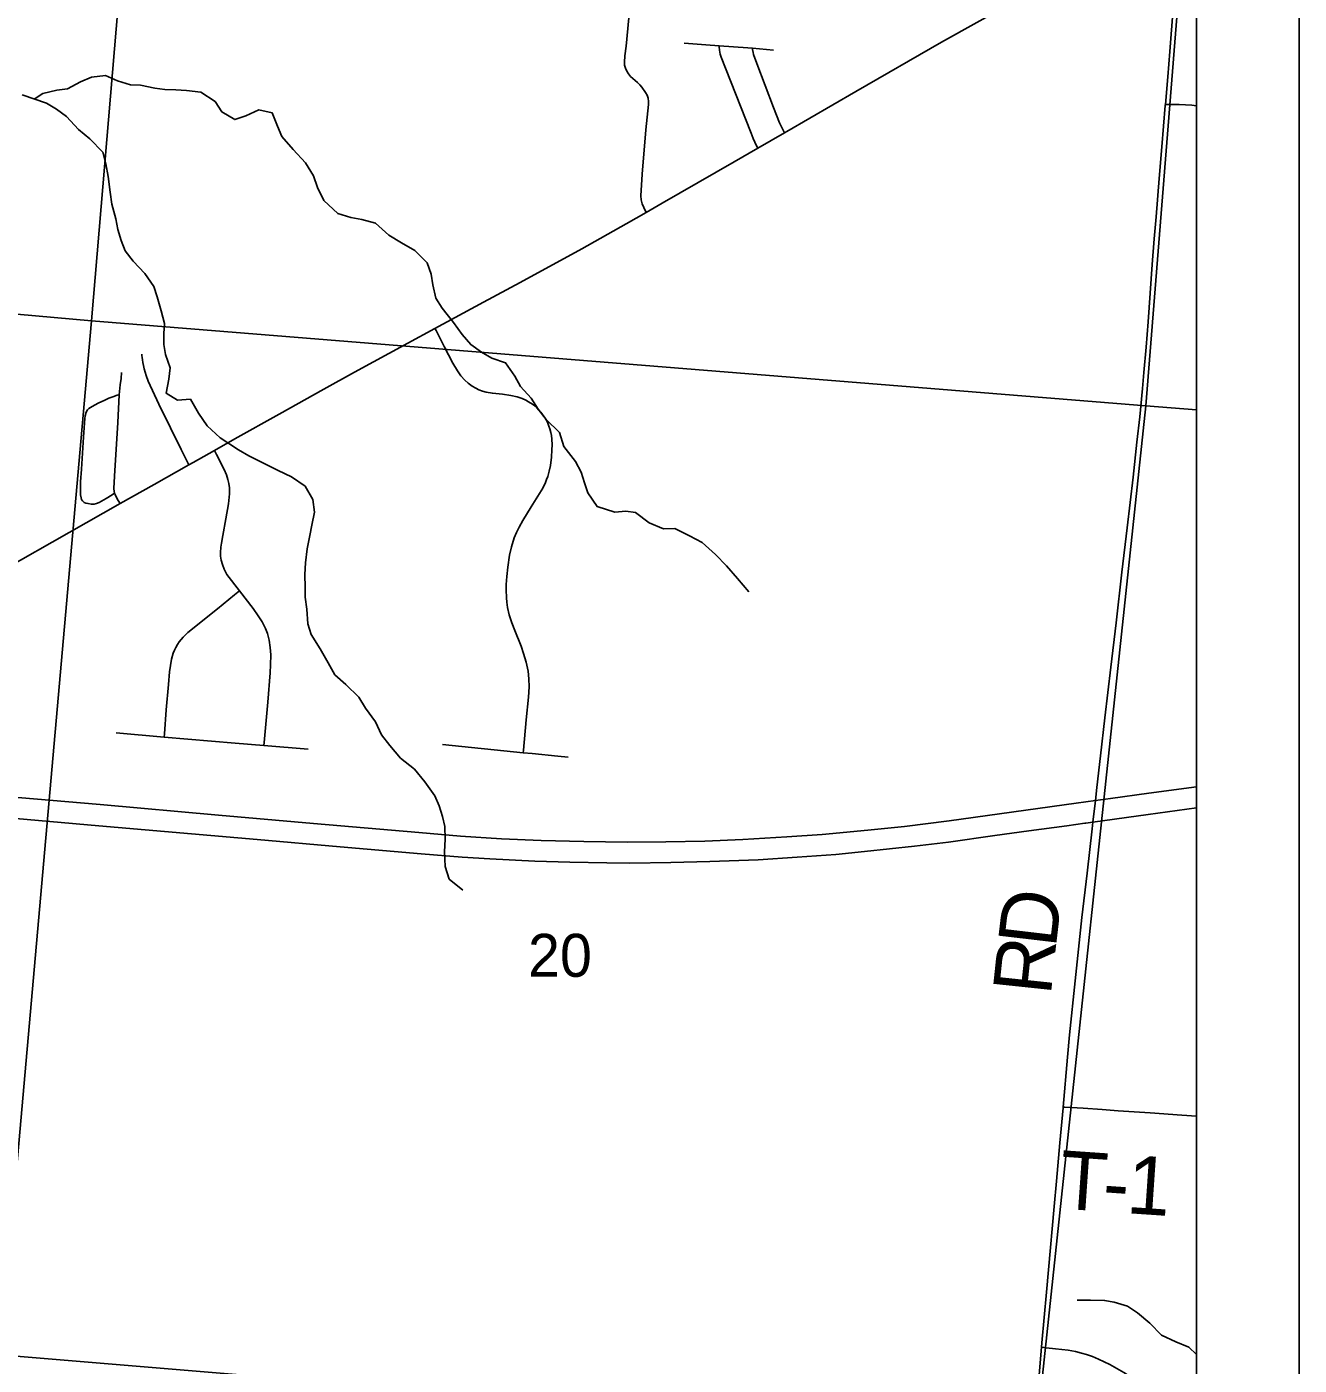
# Model space of a CAD drawing. Extents: x 831 to 1552, y 430 to 870.
# Drawn here: x 1363.98 to 1388.77, y 678.59 to 704.66 of the extents above; entities that cross this region are included whole.
import ezdxf

# ---------------------------------------------------------------- set-up
doc = ezdxf.new("R2010")
doc.units = 0
for name, color, linetype in [('GM_X_Corporation', 7, 'Continuous'), ('GM_X_County_Road', 7, 'Continuous'), ('GM_X_Interstate_Route', 7, 'Continuous'), ('GM_X_Minor_River', 7, 'Continuous'), ('GM_X_Section_Text', 7, 'Continuous'), ('GM_X_Township_Road', 7, 'Continuous'), ('GM_X_Township_Road_Text', 7, 'Continuous'), ('SH_Data', 7, 'Continuous')]:
    doc.layers.add(name, color=color, linetype=linetype)

msp = doc.modelspace()

# ---------------------------------------------------------------- linework, layer by layer
at = {"layer": 'GM_X_Corporation'}
msp.add_lwpolyline([(1386.766, 650.938), (1386.766, 724.317)], dxfattribs=at)
for points in [[(1347.89, 720.702), (1366.951, 719.126), (1365.244, 698.931), (1346.049, 700.645)], [(1386.766, 709.654), (1386.766, 717.659), (1366.951, 719.126), (1365.244, 698.931), (1385.781, 697.271)], [(1386.766, 697.192), (1386.766, 709.654), (1385.781, 697.271)], [(1346.049, 700.645), (1365.244, 698.931), (1363.462, 678.79), (1343.776, 680.603)], [(1365.244, 698.931), (1385.781, 697.271), (1383.627, 677.106), (1363.462, 678.79)], [(1386.766, 676.871), (1386.766, 697.192), (1385.781, 697.271), (1383.627, 677.106)], [(1363.462, 678.79), (1383.627, 677.106), (1381.941, 657.229), (1361.881, 658.872), (1361.646, 658.883)]]:
    msp.add_lwpolyline(points, close=True, dxfattribs=at)
at = {"layer": 'GM_X_County_Road'}
msp.add_line((1378.22, 702.291), (1378.739, 702.59), dxfattribs=at)
for points in [[(1378.739, 702.59), (1378.784, 702.616), (1380.13, 703.393), (1381.801, 704.353), (1383.804, 705.482), (1386.134, 706.793), (1386.444, 706.965)], [(1376.048, 701.038), (1376.362, 701.217), (1377.761, 702.026), (1378.22, 702.291)], [(1371.933, 698.782), (1372.882, 699.293), (1373.593, 699.676), (1374.793, 700.331), (1375.66, 700.818), (1376.048, 701.038)], [(1367.64, 696.404), (1368.035, 696.627), (1368.903, 697.113), (1369.77, 697.599), (1370.368, 697.93), (1371.405, 698.496), (1371.933, 698.782)], [(1367.14, 696.123), (1367.223, 696.169), (1367.64, 696.404)], [(1365.804, 695.368), (1366.465, 695.742), (1367.14, 696.123)], [(1358.462, 691.217), (1359.016, 691.539), (1360.01, 692.09), (1360.667, 692.459), (1361.512, 692.939), (1362.529, 693.516), (1365.804, 695.368)]]:
    msp.add_lwpolyline(points, dxfattribs=at)
at = {"layer": 'GM_X_Interstate_Route'}
msp.add_line((1384.592, 689.142), (1384.612, 689.145), dxfattribs=at)
for points in [[(1384.797, 689.584), (1385.092, 689.624), (1385.839, 689.728), (1386.766, 689.853)], [(1363.508, 689.669), (1365.413, 689.506), (1367.717, 689.301), (1369.57, 689.137), (1371.617, 688.96), (1372.43, 688.894), (1373.229, 688.842), (1374.004, 688.807), (1374.832, 688.786), (1375.68, 688.776), (1376.43, 688.779), (1377.188, 688.797), (1377.932, 688.828), (1378.787, 688.877), (1379.475, 688.925), (1380.365, 689.009), (1381.077, 689.082), (1381.95, 689.193), (1384.421, 689.534), (1384.797, 689.584)], [(1363.249, 689.278), (1365.391, 689.094), (1368.473, 688.825), (1370.087, 688.685), (1371.664, 688.549), (1372.465, 688.485), (1373.001, 688.449), (1373.878, 688.405), (1374.559, 688.385), (1375.283, 688.373), (1375.732, 688.365), (1376.525, 688.377), (1377.285, 688.397), (1378.23, 688.433), (1378.991, 688.481), (1379.743, 688.537), (1380.3, 688.593), (1381.273, 688.697), (1381.933, 688.777), (1382.838, 688.901), (1383.503, 688.993), (1384.243, 689.094), (1384.592, 689.142)], [(1384.612, 689.145), (1384.747, 689.164), (1385.821, 689.314), (1386.766, 689.443)]]:
    msp.add_lwpolyline(points, dxfattribs=at)
at = {"layer": 'GM_X_Minor_River'}
for points in [[(1364.131, 703.248), (1364.296, 703.357), (1364.57, 703.422), (1364.776, 703.45), (1365.028, 703.583), (1365.242, 703.672), (1365.516, 703.707), (1365.75, 703.605), (1366.007, 703.526), (1366.197, 703.516), (1366.478, 703.46), (1366.675, 703.435), (1366.887, 703.425), (1367.092, 703.415), (1367.373, 703.381), (1367.652, 703.203), (1367.786, 702.997), (1368.035, 702.849), (1368.249, 702.923), (1368.501, 703.041), (1368.766, 702.977), (1368.869, 702.718), (1368.95, 702.52), (1369.175, 702.267), (1369.415, 702.006), (1369.571, 701.753), (1369.644, 701.524), (1369.77, 701.272), (1370.041, 701.019), (1370.298, 700.94), (1370.51, 700.899), (1370.775, 700.828), (1371.038, 700.597), (1371.28, 700.45), (1371.544, 700.295), (1371.784, 700.057), (1371.857, 699.836), (1371.893, 699.63), (1371.95, 699.371), (1372.077, 699.172), (1372.294, 698.896), (1372.466, 698.659), (1372.63, 698.467), (1372.841, 698.321), (1373.045, 698.204), (1373.31, 698.11), (1373.489, 697.85), (1373.6, 697.651), (1373.81, 697.421), (1373.944, 697.207), (1374.101, 697.007), (1374.357, 696.754), (1374.444, 696.479), (1374.669, 696.188), (1374.78, 695.982), (1374.846, 695.776), (1374.912, 695.578), (1375.091, 695.31), (1375.439, 695.2), (1375.652, 695.22), (1375.842, 695.195), (1376.105, 694.994), (1376.385, 694.877), (1376.605, 694.882), (1376.892, 694.742), (1377.141, 694.61), (1377.397, 694.379), (1377.614, 694.157), (1377.824, 693.911), (1378.048, 693.65)], [(1363.893, 703.331), (1364.37, 703.166), (1364.566, 703.05), (1364.761, 702.911), (1364.994, 702.657), (1365.212, 702.472), (1365.467, 702.211), (1365.525, 701.983), (1365.567, 701.739), (1365.609, 701.435), (1365.644, 701.199), (1365.717, 700.917), (1365.76, 700.704), (1365.826, 700.491), (1365.899, 700.293), (1366.056, 700.093), (1366.281, 699.848), (1366.46, 699.595), (1366.526, 699.397), (1366.599, 699.123), (1366.664, 698.879), (1366.654, 698.682), (1366.652, 698.469), (1366.687, 698.271), (1366.775, 698.012), (1366.75, 697.792), (1366.701, 697.519), (1366.919, 697.38), (1367.17, 697.4), (1367.326, 697.132), (1367.498, 696.88), (1367.754, 696.649), (1368.108, 696.417), (1368.311, 696.301), (1368.598, 696.153), (1368.878, 696.013), (1369.142, 695.889), (1369.406, 695.711), (1369.554, 695.451), (1369.589, 695.2), (1369.533, 694.95), (1369.5, 694.745), (1369.444, 694.488), (1369.41, 694.215), (1369.4, 693.987), (1369.404, 693.737), (1369.409, 693.547), (1369.437, 693.311), (1369.456, 693.03), (1369.522, 692.816), (1369.701, 692.541), (1369.857, 692.266), (1369.983, 692.036), (1370.201, 691.844), (1370.449, 691.598), (1370.583, 691.384), (1370.777, 691.116), (1370.896, 690.864), (1371.053, 690.657), (1371.262, 690.412), (1371.533, 690.196), (1371.735, 689.951), (1371.93, 689.675), (1372.018, 689.484), (1372.084, 689.271), (1372.127, 689.08), (1372.132, 688.83), (1372.121, 688.587), (1372.133, 688.298), (1372.213, 688.054), (1372.477, 687.839)], [(1386.766, 678.795), (1386.619, 678.941), (1386.362, 679.042), (1386.083, 679.175), (1385.857, 679.405), (1385.617, 679.605), (1385.421, 679.737), (1385.164, 679.816), (1384.974, 679.848), (1384.701, 679.851), (1384.442, 679.854)]]:
    msp.add_lwpolyline(points, dxfattribs=at)
at = {"layer": 'GM_X_Township_Road'}
for p, q in [((1378.117, 704.237), (1378.527, 704.201)), ((1365.726, 690.903), (1366.662, 690.822)), ((1368.604, 690.654), (1369.467, 690.584)), ((1372.083, 690.676), (1373.653, 690.517))]:
    msp.add_line(p, q, dxfattribs=at)
for points in [[(1386.16, 703.143), (1386.205, 703.68), (1386.246, 704.176), (1386.309, 705.011)], [(1376.048, 701.038), (1376.041, 701.053), (1376.002, 701.135), (1375.971, 701.207), (1375.951, 701.282), (1375.943, 701.36), (1375.972, 701.785), (1376.042, 702.648), (1376.095, 703.141), (1376.096, 703.202), (1376.088, 703.264), (1376.067, 703.322), (1376.036, 703.375), (1375.966, 703.477), (1375.926, 703.525), (1375.881, 703.568), (1375.786, 703.647), (1375.742, 703.69), (1375.704, 703.738), (1375.671, 703.791), (1375.645, 703.847), (1375.628, 703.907), (1375.623, 703.968), (1375.633, 704.092), (1375.657, 704.276), (1375.712, 704.83)], [(1376.785, 704.339), (1377.208, 704.303), (1377.471, 704.284)], [(1378.22, 702.291), (1378.198, 702.337), (1378.129, 702.48), (1378.093, 702.585), (1377.693, 703.603), (1377.51, 704.065), (1377.49, 704.123), (1377.475, 704.198), (1377.472, 704.264), (1377.471, 704.284)], [(1377.471, 704.284), (1378.025, 704.245), (1378.117, 704.237)], [(1378.739, 702.59), (1378.706, 702.658), (1378.646, 702.783), (1378.53, 703.082), (1378.205, 703.941), (1378.139, 704.114), (1378.13, 704.153), (1378.121, 704.21), (1378.117, 704.237)], [(1384.169, 683.611), (1384.254, 684.587), (1384.292, 685.021), (1384.4, 686.071), (1384.466, 686.689), (1384.533, 687.307), (1384.635, 688.17), (1384.732, 689.035), (1384.747, 689.164), (1384.797, 689.584), (1384.827, 689.837), (1384.897, 690.454), (1384.983, 691.195), (1385.099, 692.181), (1385.199, 693.045), (1385.311, 694.033), (1385.412, 694.897), (1385.529, 695.884), (1385.605, 696.563), (1385.661, 697.057), (1385.712, 697.613), (1385.739, 697.922), (1385.783, 698.417), (1385.822, 698.912), (1385.903, 700.028), (1385.943, 700.523), (1385.978, 700.956), (1386.039, 701.699), (1386.088, 702.319), (1386.158, 703.123), (1386.16, 703.143)], [(1386.16, 703.143), (1386.217, 703.142), (1386.428, 703.139), (1386.677, 703.126), (1386.766, 703.118)], [(1373.653, 690.517), (1373.658, 690.569), (1373.712, 691.154), (1373.756, 691.597), (1373.769, 691.801), (1373.761, 691.956), (1373.748, 692.103), (1373.71, 692.28), (1373.661, 692.448), (1373.612, 692.592), (1373.489, 692.899), (1373.432, 693.044), (1373.381, 693.199), (1373.348, 693.345), (1373.334, 693.451), (1373.329, 693.53), (1373.321, 693.688), (1373.321, 693.794), (1373.334, 693.949), (1373.353, 694.131), (1373.386, 694.362), (1373.424, 694.528), (1373.478, 694.699), (1373.525, 694.803), (1373.574, 694.912), (1373.647, 695.042), (1373.807, 695.303), (1374.033, 695.667), (1374.09, 695.779), (1374.109, 695.836), (1374.131, 695.896), (1374.158, 695.999), (1374.183, 696.111), (1374.202, 696.271), (1374.213, 696.418), (1374.218, 696.516), (1374.213, 696.625), (1374.204, 696.695), (1374.191, 696.755), (1374.174, 696.823), (1374.155, 696.877), (1374.134, 696.934), (1374.101, 696.997), (1374.068, 697.049), (1374.03, 697.103), (1373.995, 697.147), (1373.949, 697.198), (1373.903, 697.25), (1373.835, 697.307), (1373.758, 697.353), (1373.704, 697.386), (1373.633, 697.416), (1373.533, 697.448), (1373.413, 697.473), (1373.25, 697.497), (1373.054, 697.519), (1372.932, 697.541), (1372.861, 697.56), (1372.79, 697.587), (1372.731, 697.614), (1372.657, 697.658), (1372.584, 697.712), (1372.519, 697.772), (1372.44, 697.856), (1372.372, 697.957), (1372.285, 698.104), (1372.113, 698.43), (1371.956, 698.737), (1371.933, 698.782)], [(1367.14, 696.123), (1367.108, 696.188), (1366.993, 696.422), (1366.786, 696.843), (1366.558, 697.305), (1366.351, 697.754), (1366.307, 697.862), (1366.271, 697.992), (1366.258, 698.056), (1366.247, 698.114), (1366.238, 698.167), (1366.232, 698.212), (1366.228, 698.251), (1366.226, 698.276)], [(1365.785, 697.487), (1365.806, 697.682), (1365.82, 697.804), (1365.832, 697.924)], [(1365.694, 695.57), (1365.647, 695.541), (1365.528, 695.467), (1365.397, 695.389), (1365.345, 695.369), (1365.298, 695.36), (1365.24, 695.36), (1365.177, 695.368), (1365.136, 695.377), (1365.105, 695.393), (1365.072, 695.422), (1365.053, 695.449), (1365.041, 695.48), (1365.03, 695.541), (1365.029, 695.604), (1365.034, 695.791), (1365.052, 696.04), (1365.07, 696.352), (1365.092, 696.664), (1365.117, 697.028), (1365.122, 697.078), (1365.142, 697.151), (1365.169, 697.196), (1365.195, 697.222), (1365.226, 697.241), (1365.305, 697.283), (1365.39, 697.328), (1365.494, 697.379), (1365.585, 697.419), (1365.659, 697.448), (1365.746, 697.478), (1365.785, 697.487)], [(1365.694, 695.57), (1365.688, 695.603), (1365.682, 695.663), (1365.693, 695.906), (1365.755, 696.949), (1365.785, 697.487)], [(1368.127, 693.669), (1367.883, 693.987), (1367.832, 694.092), (1367.794, 694.184), (1367.771, 694.265), (1367.76, 694.344), (1367.76, 694.418), (1367.767, 694.52), (1367.774, 694.598), (1367.801, 694.748), (1367.862, 695.07), (1367.913, 695.363), (1367.934, 695.556), (1367.934, 695.678), (1367.92, 695.76), (1367.903, 695.838), (1367.872, 695.926), (1367.828, 696.035), (1367.679, 696.327), (1367.64, 696.404)], [(1365.804, 695.368), (1365.767, 695.429), (1365.718, 695.514), (1365.703, 695.544), (1365.694, 695.57)], [(1366.662, 690.822), (1366.667, 690.886), (1366.7, 691.353), (1366.746, 691.846), (1366.767, 692.092), (1366.782, 692.215), (1366.805, 692.336), (1366.838, 692.455), (1366.861, 692.513), (1366.887, 692.568), (1366.918, 692.622), (1366.952, 692.673), (1367.03, 692.77), (1367.119, 692.855), (1367.698, 693.32), (1368.033, 693.593), (1368.127, 693.669)], [(1368.604, 690.654), (1368.61, 690.713), (1368.677, 691.501), (1368.725, 692.071), (1368.728, 692.231), (1368.735, 692.421), (1368.725, 692.564), (1368.705, 692.71), (1368.674, 692.839), (1368.633, 692.938), (1368.569, 693.067), (1368.491, 693.185), (1368.392, 693.325), (1368.127, 693.669)], [(1366.662, 690.822), (1367.119, 690.782), (1368.046, 690.7), (1368.604, 690.654)], [(1373.653, 690.517), (1373.826, 690.499), (1374.325, 690.45), (1374.528, 690.433)], [(1383.745, 678.936), (1383.752, 679.02), (1383.799, 679.515), (1383.843, 680.009), (1383.882, 680.443), (1383.995, 681.679), (1384.04, 682.174), (1384.106, 682.916), (1384.167, 683.597), (1384.169, 683.611)], [(1384.169, 683.611), (1384.198, 683.61), (1384.556, 683.591), (1384.928, 683.565), (1385.239, 683.544), (1385.55, 683.523), (1385.86, 683.502), (1386.481, 683.458), (1386.766, 683.437)], [(1383.075, 670.4), (1383.082, 670.423), (1383.093, 670.483), (1383.106, 670.569), (1383.139, 670.893), (1383.164, 671.271), (1383.189, 671.655), (1383.21, 672.213), (1383.232, 672.645), (1383.27, 673.264), (1383.327, 673.886), (1383.413, 674.997), (1383.478, 675.739), (1383.531, 676.368), (1383.576, 676.934), (1383.611, 677.348), (1383.701, 678.4), (1383.745, 678.936)], [(1383.745, 678.936), (1383.837, 678.927), (1384.021, 678.908), (1384.266, 678.877), (1384.409, 678.852), (1384.529, 678.824), (1384.625, 678.797), (1384.742, 678.757), (1384.855, 678.708), (1385.076, 678.601), (1385.352, 678.444), (1385.502, 678.35), (1385.707, 678.222), (1385.907, 678.104)]]:
    msp.add_lwpolyline(points, dxfattribs=at)
at = {"layer": 'SH_Data'}
for p, q in [((1388.766, 788.938), (1388.766, 648.938)), ((1386.766, 786.938), (1386.766, 650.938))]:
    msp.add_line(p, q, dxfattribs=at)

# ---------------------------------------------------------------- texts
at = {"layer": 'GM_X_Section_Text'}
msp.add_text('20', height=0.8371, rotation=0, dxfattribs=at).set_placement((1373.746, 686.152))
at = {"layer": 'GM_X_Township_Road_Text'}
for s, rotation, p in [('D', 83.304, (1384.024, 686.697)), ('R', 83.9783, (1383.926, 685.772)), ('T', 356.0564, (1384.068, 681.641)), ('1', 356.1234, (1385.383, 681.55)), ('-', 356.07, (1384.916, 681.583))]:
    msp.add_text(s, height=1.136, rotation=rotation, dxfattribs=at).set_placement(p)

doc.saveas('drawing.dxf')
